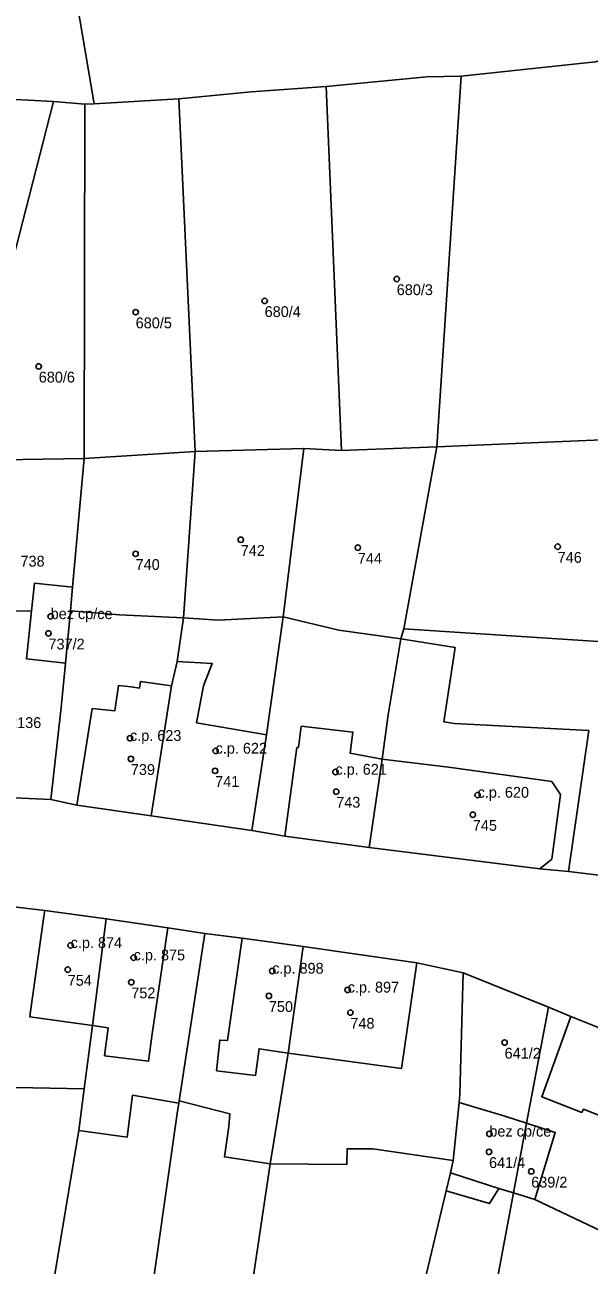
# Model space of a CAD drawing. Extents: x -878211 to -870363, y -1058464 to -1052522.
# Drawn here: x -874575.8 to -874523.6, y -1056540.4 to -1056425.6 of the extents above; entities that cross this region are included whole.
import ezdxf

# ---------------------------------------------------------------- set-up
doc = ezdxf.new("R2010")
doc.units = 0
for name, color, linetype in [('Vrstva 50', 7, 'Continuous'), ('Vrstva 51', 7, 'Continuous'), ('Vrstva 52', 7, 'Continuous')]:
    doc.layers.add(name, color=color, linetype=linetype)

msp = doc.modelspace()

# ---------------------------------------------------------------- linework, layer by layer
at = {"layer": 'Vrstva 50'}
for centre in [(-874541.41, -1056449.10994), (-874553.63, -1056451.13994), (-874565.56, -1056452.17994), (-874574.53, -1056457.19994), (-874555.84, -1056473.23994), (-874545.01, -1056473.96994), (-874526.52, -1056473.87994), (-874565.57, -1056474.53994), (-874573.43, -1056480.32994), (-874573.63, -1056481.89994), (-874566.09, -1056491.59994), (-874566.01, -1056493.50994), (-874558.17, -1056492.77994), (-874558.21, -1056494.61994), (-874547.08, -1056494.72994), (-874547.01, -1056496.53994), (-874533.93, -1056496.85994), (-874534.37, -1056498.67994), (-874571.58, -1056510.76994), (-874565.75, -1056511.90994), (-874571.85, -1056513.01994), (-874552.93, -1056513.13994), (-874565.97, -1056514.17994), (-874553.24, -1056515.43994), (-874545.95, -1056514.88994), (-874545.7, -1056516.98994), (-874531.43, -1056519.75994), (-874532.84, -1056528.20994), (-874532.87, -1056529.87994), (-874528.97, -1056531.68994)]:
    msp.add_circle(centre, 0.25, dxfattribs=at)
at = {"layer": 'Vrstva 51'}
for points in [[(-874506.63, -1056424.46), (-874505.5, -1056424.13), (-874490.03, -1056419.45), (-874482.07, -1056416.75), (-874480.73, -1056416.32), (-874484.53, -1056404.72), (-874506.28, -1056409.52), (-874544.06, -1056414.29), (-874571.8, -1056418.71), (-874569.39, -1056432.89), (-874561.56, -1056432.43), (-874554.89, -1056431.78), (-874547.93, -1056431.29), (-874538.64, -1056430.41), (-874535.46, -1056430.33), (-874523.03, -1056429.03), (-874509.91, -1056425.43)], [(-874583.57, -1056418.49), (-874586.64, -1056418.34), (-874591.8, -1056418.17), (-874591.85, -1056419.68), (-874597.02, -1056419.51), (-874597.28, -1056427.58), (-874596.8, -1056427.63), (-874596.8, -1056431.5), (-874588.16, -1056431.92), (-874587.55, -1056431.96), (-874575.47, -1056432.55), (-874573.16, -1056432.7), (-874570.27, -1056432.92), (-874569.39, -1056432.89), (-874571.8, -1056418.71), (-874572.76, -1056413.05), (-874583.42, -1056409.27)], [(-874509.91, -1056425.43), (-874523.03, -1056429.03), (-874535.46, -1056430.33), (-874537.69, -1056464.65), (-874513.7, -1056463.63), (-874506.09, -1056462.44), (-874506.63, -1056424.46)], [(-874547.93, -1056431.29), (-874546.52, -1056464.97), (-874537.69, -1056464.65), (-874535.46, -1056430.33), (-874538.64, -1056430.41)], [(-874554.89, -1056431.78), (-874561.56, -1056432.43), (-874560.05, -1056465.08), (-874550.01, -1056464.79), (-874546.52, -1056464.97), (-874547.93, -1056431.29)], [(-874575.47, -1056432.55), (-874587.55, -1056431.96), (-874588.16, -1056431.92), (-874588.96, -1056435.96), (-874595.05, -1056462.65), (-874595.59, -1056464.97), (-874581.72, -1056465.9), (-874573.16, -1056432.7)], [(-874573.16, -1056432.7), (-874581.72, -1056465.9), (-874570.34, -1056465.73), (-874570.27, -1056432.92)], [(-874569.39, -1056432.89), (-874570.27, -1056432.92), (-874570.34, -1056465.73), (-874560.05, -1056465.08), (-874561.56, -1056432.43)], [(-874514.71, -1056483.17), (-874514.72, -1056478.57), (-874513.7, -1056463.63), (-874537.69, -1056464.65), (-874540.74, -1056481.47)], [(-874551.92, -1056480.37), (-874550.01, -1056464.79), (-874560.05, -1056465.08), (-874561.14, -1056480.46), (-874557.9, -1056480.67)], [(-874537.69, -1056464.65), (-874546.52, -1056464.97), (-874550.01, -1056464.79), (-874551.92, -1056480.37), (-874546.76, -1056481.61), (-874541.04, -1056482.41), (-874540.74, -1056481.47)], [(-874575.19, -1056479.82), (-874574.91, -1056477.25), (-874571.4, -1056477.64), (-874570.34, -1056465.73), (-874581.72, -1056465.9), (-874582.45, -1056479.82), (-874582.05, -1056479.85)], [(-874571.4, -1056477.64), (-874571.59, -1056479.8), (-874567.05, -1056480.18), (-874561.14, -1056480.46), (-874560.05, -1056465.08), (-874570.34, -1056465.73)], [(-874571.4, -1056477.64), (-874574.91, -1056477.25), (-874575.19, -1056479.82), (-874575.67, -1056484.25), (-874572.07, -1056484.65), (-874571.59, -1056479.8)], [(-874575.19, -1056479.82), (-874582.05, -1056479.85), (-874582.45, -1056479.82), (-874585.5, -1056479.63), (-874585.64, -1056485.03), (-874585.85, -1056486.25), (-874586.04, -1056487.32), (-874586.73, -1056496.31), (-874576.8, -1056497.11), (-874573.41, -1056497.27), (-874572.47, -1056488.75), (-874572.07, -1056484.65), (-874575.67, -1056484.25)], [(-874561.14, -1056480.46), (-874567.05, -1056480.18), (-874571.59, -1056479.8), (-874572.07, -1056484.65), (-874572.47, -1056488.75), (-874573.41, -1056497.27), (-874571, -1056497.81), (-874564.14, -1056498.79), (-874562.24, -1056486.74), (-874561.73, -1056484.51)], [(-874561.14, -1056480.46), (-874561.73, -1056484.51), (-874562.24, -1056486.74), (-874564.14, -1056498.79), (-874554.82, -1056500.14), (-874553.45, -1056491.28), (-874551.92, -1056480.37), (-874557.9, -1056480.67)], [(-874541.04, -1056482.41), (-874546.76, -1056481.61), (-874551.92, -1056480.37), (-874553.45, -1056491.28), (-874554.82, -1056500.14), (-874551.76, -1056500.67), (-874543.95, -1056501.72), (-874542.75, -1056493.53), (-874542.19, -1056489.45)], [(-874540.74, -1056481.47), (-874541.04, -1056482.41), (-874536.01, -1056483.21), (-874537.05, -1056490.1), (-874536.06, -1056490.23), (-874523.64, -1056490.9), (-874525.53, -1056503.93), (-874520.11, -1056504.57), (-874519.11, -1056504.61), (-874515.7, -1056503.29), (-874514.7, -1056486.72), (-874514.71, -1056483.17)], [(-874541.04, -1056482.41), (-874542.19, -1056489.45), (-874542.75, -1056493.53), (-874543.95, -1056501.72), (-874528.18, -1056503.7), (-874525.53, -1056503.93), (-874523.64, -1056490.9), (-874536.06, -1056490.23), (-874537.05, -1056490.1), (-874536.01, -1056483.21)], [(-874570.32, -1056524.04), (-874569.56, -1056518.17), (-874568.29, -1056508.31), (-874573.96, -1056507.53), (-874577.6, -1056507.11), (-874579.86, -1056522.5), (-874579.86, -1056523.86)], [(-874561.57, -1056525.37), (-874561.54, -1056525.16), (-874559.16, -1056509.66), (-874562.6, -1056509.14), (-874568.29, -1056508.31), (-874569.56, -1056518.17), (-874570.32, -1056524.04), (-874570.82, -1056527.91), (-874566.34, -1056528.51), (-874565.86, -1056524.64)], [(-874553.13, -1056530.99), (-874552.67, -1056528.17), (-874551.46, -1056520.75), (-874550.06, -1056510.88), (-874555.71, -1056510.1), (-874559.16, -1056509.66), (-874561.54, -1056525.16), (-874556.84, -1056526.37), (-874556.95, -1056527.54), (-874557.35, -1056530.35)], [(-874553.13, -1056530.99), (-874546.04, -1056531.06), (-874546, -1056529.59), (-874543.62, -1056529.61), (-874536.2, -1056530.68), (-874535.64, -1056525.3), (-874535.57, -1056524.57), (-874535.25, -1056513.32), (-874539.56, -1056512.39), (-874550.06, -1056510.88), (-874551.46, -1056520.75), (-874552.67, -1056528.17)], [(-874527.37, -1056516.49), (-874535.25, -1056513.32), (-874535.57, -1056524.57), (-874535.64, -1056525.3), (-874531.42, -1056526.57), (-874529.39, -1056527.23)], [(-874520.66, -1056538.08), (-874519.79, -1056535.06), (-874517.46, -1056529.22), (-874516.68, -1056527.23), (-874514.5, -1056521.67), (-874525.31, -1056517.35), (-874527.37, -1056516.49), (-874529.39, -1056527.23), (-874526.74, -1056528.08), (-874528.64, -1056534.27)], [(-874580.15, -1056526.19), (-874586.74, -1056569.75), (-874578.03, -1056571.11), (-874570.82, -1056527.91), (-874570.32, -1056524.04), (-874579.86, -1056523.86)], [(-874570.82, -1056527.91), (-874578.03, -1056571.11), (-874577.85, -1056571.11), (-874568.31, -1056572.74), (-874561.72, -1056526.32), (-874561.57, -1056525.37), (-874565.86, -1056524.64), (-874566.34, -1056528.51)], [(-874561.72, -1056526.32), (-874568.31, -1056572.74), (-874559.55, -1056574), (-874553.13, -1056530.99), (-874557.35, -1056530.35), (-874556.95, -1056527.54), (-874556.84, -1056526.37), (-874561.54, -1056525.16), (-874561.57, -1056525.37)], [(-874530.6, -1056533.68), (-874529.39, -1056527.23), (-874531.42, -1056526.57), (-874535.64, -1056525.3), (-874536.2, -1056530.68), (-874536.45, -1056531.83), (-874536.83, -1056533.48), (-874532.82, -1056534.66), (-874531.97, -1056533.27)], [(-874530.6, -1056533.68), (-874528.64, -1056534.27), (-874526.74, -1056528.08), (-874529.39, -1056527.23)], [(-874553.13, -1056530.99), (-874559.55, -1056574), (-874557.16, -1056574.77), (-874547.1, -1056576.67), (-874536.83, -1056533.48), (-874536.45, -1056531.83), (-874536.2, -1056530.68), (-874543.62, -1056529.61), (-874546, -1056529.59), (-874546.04, -1056531.06)], [(-874530.6, -1056533.68), (-874531.97, -1056533.27), (-874532.82, -1056534.66), (-874536.83, -1056533.48), (-874547.1, -1056576.67), (-874542.4, -1056577.56), (-874537.13, -1056556.99), (-874535.12, -1056557.72)], [(-874528.64, -1056534.27), (-874530.6, -1056533.68), (-874535.12, -1056557.72), (-874527.37, -1056560.52), (-874523.57, -1056546.74), (-874522.16, -1056542.69), (-874521.24, -1056540.06), (-874520.66, -1056538.08)]]:
    msp.add_lwpolyline(points, close=True, dxfattribs=at)
for points in [[(-874520.11, -1056504.57), (-874525.53, -1056503.93), (-874528.18, -1056503.7), (-874543.95, -1056501.72), (-874551.76, -1056500.67), (-874554.82, -1056500.14), (-874564.14, -1056498.79), (-874571, -1056497.81), (-874573.41, -1056497.27), (-874576.8, -1056497.11), (-874586.73, -1056496.31), (-874592.41, -1056495.69), (-874596.73, -1056495.3), (-874608.98, -1056494.31), (-874615.54, -1056493.73), (-874618.35, -1056493.44), (-874621.12, -1056493.2), (-874631.31, -1056492.35), (-874634.23, -1056492.09), (-874640.95, -1056491.51), (-874651.42, -1056490.62), (-874651.63, -1056491.41), (-874658.14, -1056492.03), (-874672.92, -1056493.55)], [(-874577.6, -1056507.11), (-874573.96, -1056507.53), (-874568.29, -1056508.31), (-874562.6, -1056509.14), (-874559.16, -1056509.66), (-874555.71, -1056510.1), (-874550.06, -1056510.88), (-874539.56, -1056512.39), (-874535.25, -1056513.32), (-874527.37, -1056516.49), (-874525.31, -1056517.35), (-874514.5, -1056521.67)]]:
    msp.add_lwpolyline(points, dxfattribs=at)
at = {"layer": 'Vrstva 52'}
for points in [[(-874575.19, -1056479.82), (-874575.67, -1056484.25), (-874572.07, -1056484.65), (-874571.59, -1056479.8), (-874571.4, -1056477.64), (-874574.91, -1056477.25)], [(-874564.14, -1056498.79), (-874554.82, -1056500.14), (-874553.45, -1056491.28), (-874559.93, -1056490.17), (-874559.29, -1056486.75), (-874558.48, -1056484.7), (-874561.73, -1056484.51), (-874562.24, -1056486.74)], [(-874569.59, -1056488.85), (-874571, -1056497.81), (-874564.14, -1056498.79), (-874562.24, -1056486.74), (-874565.12, -1056486.35), (-874565.2, -1056486.97), (-874565.97, -1056486.86), (-874567.15, -1056486.71), (-874567.48, -1056489.06)], [(-874551.76, -1056500.67), (-874543.95, -1056501.72), (-874542.75, -1056493.53), (-874545.71, -1056493), (-874545.47, -1056491.04), (-874550.25, -1056490.5), (-874550.5, -1056492.46), (-874550.64, -1056492.47)], [(-874543.95, -1056501.72), (-874528.18, -1056503.7), (-874527.07, -1056502.79), (-874526.26, -1056496.8), (-874527.07, -1056495.61), (-874536.63, -1056494.27), (-874542.75, -1056493.53)], [(-874568.29, -1056508.31), (-874573.96, -1056507.53), (-874574.06, -1056508.11), (-874575.33, -1056517.1), (-874575.37, -1056517.37), (-874569.56, -1056518.17)], [(-874569.56, -1056518.17), (-874568.12, -1056518.39), (-874568.44, -1056520.98), (-874564.37, -1056521.49), (-874564.05, -1056518.95), (-874562.6, -1056509.14), (-874568.29, -1056508.31)], [(-874558.09, -1056522.37), (-874554.49, -1056522.82), (-874554.15, -1056520.33), (-874551.46, -1056520.75), (-874550.06, -1056510.88), (-874555.71, -1056510.1), (-874557.06, -1056519.57), (-874557.78, -1056519.53)], [(-874550.06, -1056510.88), (-874551.46, -1056520.75), (-874540.98, -1056522.17), (-874539.56, -1056512.39)], [(-874514.5, -1056521.67), (-874525.31, -1056517.35), (-874528, -1056524.77), (-874524.3, -1056526.22), (-874524.14, -1056525.94), (-874520.86, -1056527.21), (-874520.33, -1056525.7), (-874516.68, -1056527.23)], [(-874528.64, -1056534.27), (-874526.74, -1056528.08), (-874529.39, -1056527.23), (-874531.42, -1056526.57), (-874535.64, -1056525.3), (-874536.2, -1056530.68), (-874536.45, -1056531.83), (-874531.97, -1056533.27), (-874530.6, -1056533.68)]]:
    msp.add_lwpolyline(points, close=True, dxfattribs=at)

# ---------------------------------------------------------------- texts
at = {"layer": 'Vrstva 50'}
for s, p in [('680/3', (-874541.41, -1056450.599)), ('680/4', (-874553.63, -1056452.629)), ('680/5', (-874565.56, -1056453.669)), ('680/6', (-874574.53, -1056458.689)), ('742', (-874555.84, -1056474.729)), ('738', (-874576.22, -1056475.719)), ('740', (-874565.57, -1056476.029)), ('744', (-874545.01, -1056475.459)), ('746', (-874526.52, -1056475.369)), ('bez cp/ce', (-874573.43, -1056480.58)), ('737/2', (-874573.63, -1056483.389)), ('c.p. 2136', (-874579.8, -1056490.659)), ('c.p. 623', (-874566.09, -1056491.85)), ('c.p. 622', (-874558.17, -1056493.03)), ('739', (-874566.01, -1056494.999)), ('c.p. 621', (-874547.08, -1056494.98)), ('741', (-874558.21, -1056496.109)), ('743', (-874547.01, -1056498.029)), ('c.p. 620', (-874533.93, -1056497.11)), ('745', (-874534.37, -1056500.169)), ('c.p. 874', (-874571.58, -1056511.02)), ('c.p. 875', (-874565.75, -1056512.159)), ('c.p. 898', (-874552.93, -1056513.389)), ('754', (-874571.85, -1056514.509)), ('c.p. 897', (-874545.95, -1056515.139)), ('752', (-874565.97, -1056515.669)), ('750', (-874553.24, -1056516.929)), ('748', (-874545.7, -1056518.479)), ('641/2', (-874531.43, -1056521.249)), ('bez cp/ce', (-874532.84, -1056528.46)), ('641/4', (-874532.87, -1056531.369)), ('639/2', (-874528.97, -1056533.179))]:
    msp.add_text(s, height=0.999996, dxfattribs=at).set_placement(p)

doc.saveas('drawing.dxf')
